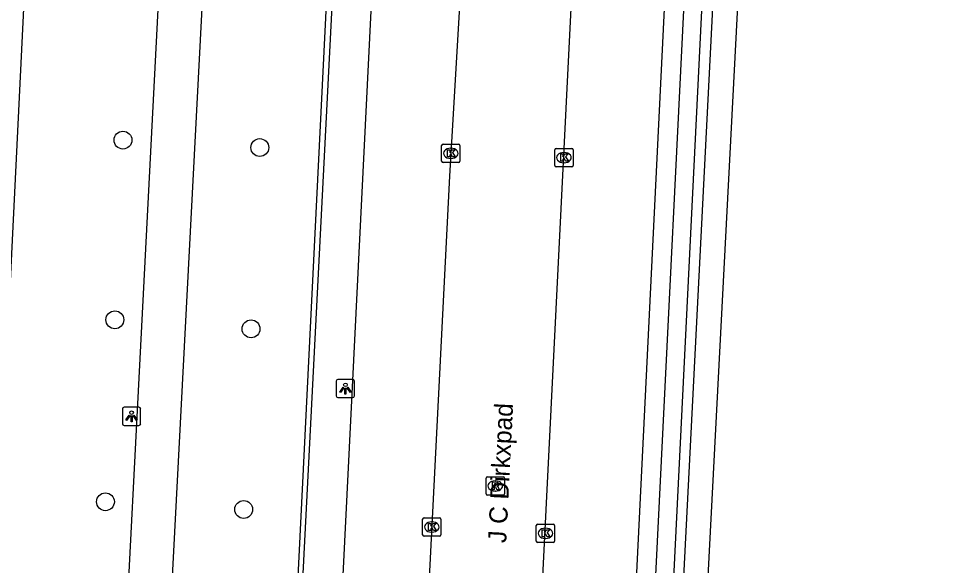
# Model space of a CAD drawing. Extents: x 161761 to 162722, y 384793 to 385405.
# Drawn here: x 162374.6 to 162426.2, y 385154.5 to 385184.4 of the extents above; entities that cross this region are included whole.
import ezdxf

# ---------------------------------------------------------------- set-up
doc = ezdxf.new("R2010")
doc.units = 0
for name, color, linetype in [('IMGEO_Boom', 7, 'Continuous'), ('IMGEO_Groenvoorziening', 7, 'Continuous'), ('IMGEO_Kolk', 7, 'Continuous'), ('IMGEO_Lichtpunt', 7, 'Continuous'), ('IMGEO_Loofbos', 7, 'Continuous'), ('IMGEO_Openbare_ruimte_label', 7, 'Continuous'), ('IMGEO_Parkeervlak_open', 7, 'Continuous'), ('IMGEO_Rijbaan_lokaal_open', 7, 'Continuous'), ('IMGEO_Rioolput', 7, 'Continuous'), ('IMGEO_Voetpad_open', 7, 'Continuous'), ('IMGEO_Waterloop', 7, 'Continuous')]:
    doc.layers.add(name, color=color, linetype=linetype)

msp = doc.modelspace()

# ---------------------------------------------------------------- linework, layer by layer
at = {"layer": 'IMGEO_Boom'}
for centre in [(162380.34, 385177.754), (162387.833, 385177.345), (162379.898, 385167.921), (162387.354, 385167.423), (162379.381, 385157.961), (162386.951, 385157.54)]:
    msp.add_circle(centre, 0.489, dxfattribs=at)
at = {"layer": 'IMGEO_Groenvoorziening'}
msp.add_lwpolyline([(162419.401, 385355.707), (162414.261, 385250), (162407.783, 385119.36)], dxfattribs=at)
at = {"layer": 'IMGEO_Kolk'}
for p, q in [((162397.792, 385176.604), (162397.792, 385177.456)), ((162397.867, 385177.53), (162398.719, 385177.53)), ((162398.28, 385177.31), (162398.305, 385177.31)), ((162398.793, 385177.456), (162398.793, 385176.604)), ((162403.989, 385176.369), (162403.989, 385177.221)), ((162404.064, 385177.295), (162404.916, 385177.295)), ((162404.99, 385177.221), (162404.99, 385176.369)), ((162398.303, 385176.75), (162398.278, 385176.75)), ((162404.477, 385177.075), (162404.502, 385177.075)), ((162398.719, 385176.53), (162397.867, 385176.53)), ((162404.916, 385176.295), (162404.064, 385176.295)), ((162404.5, 385176.515), (162404.475, 385176.515)), ((162396.826, 385157.08), (162397.678, 385157.08)), ((162396.751, 385156.154), (162396.751, 385157.006)), ((162397.239, 385156.86), (162397.264, 385156.86)), ((162397.752, 385157.006), (162397.752, 385156.154)), ((162402.974, 385155.807), (162402.974, 385156.659)), ((162403.049, 385156.733), (162403.901, 385156.733)), ((162403.975, 385156.659), (162403.975, 385155.807)), ((162397.678, 385156.08), (162396.826, 385156.08)), ((162397.262, 385156.3), (162397.237, 385156.3)), ((162403.462, 385156.513), (162403.487, 385156.513)), ((162403.901, 385155.733), (162403.049, 385155.733)), ((162403.485, 385155.953), (162403.46, 385155.953))]:
    msp.add_line(p, q, dxfattribs=at)
for points in [[(162397.792, 385176.604), (162397.792, 385177.456)], [(162397.867, 385177.53), (162398.719, 385177.53)], [(162398.113, 385177.23), (162398.236, 385177.23), (162398.236, 385177.079), (162398.366, 385177.23), (162398.53, 385177.23), (162398.384, 385177.079), (162398.537, 385176.83), (162398.385, 385176.83), (162398.3, 385176.994), (162398.236, 385176.927), (162398.236, 385176.83), (162398.113, 385176.83), (162398.113, 385177.23)], [(162398.793, 385177.456), (162398.793, 385176.604)], [(162403.989, 385176.369), (162403.989, 385177.221)], [(162404.064, 385177.295), (162404.916, 385177.295)], [(162404.99, 385177.221), (162404.99, 385176.369)], [(162404.31, 385176.995), (162404.433, 385176.995), (162404.433, 385176.844), (162404.563, 385176.995), (162404.727, 385176.995), (162404.581, 385176.844), (162404.734, 385176.595), (162404.582, 385176.595), (162404.497, 385176.759), (162404.433, 385176.692), (162404.433, 385176.595), (162404.31, 385176.595), (162404.31, 385176.995)], [(162398.719, 385176.53), (162397.867, 385176.53)], [(162404.916, 385176.295), (162404.064, 385176.295)], [(162396.826, 385157.08), (162397.678, 385157.08)], [(162396.751, 385156.154), (162396.751, 385157.006)], [(162397.072, 385156.78), (162397.195, 385156.78), (162397.195, 385156.629), (162397.325, 385156.78), (162397.489, 385156.78), (162397.343, 385156.629), (162397.496, 385156.38), (162397.344, 385156.38), (162397.259, 385156.544), (162397.195, 385156.477), (162397.195, 385156.38), (162397.072, 385156.38), (162397.072, 385156.78)], [(162397.752, 385157.006), (162397.752, 385156.154)], [(162402.974, 385155.807), (162402.974, 385156.659)], [(162403.049, 385156.733), (162403.901, 385156.733)], [(162403.975, 385156.659), (162403.975, 385155.807)], [(162397.678, 385156.08), (162396.826, 385156.08)], [(162403.295, 385156.433), (162403.418, 385156.433), (162403.418, 385156.282), (162403.548, 385156.433), (162403.712, 385156.433), (162403.566, 385156.282), (162403.719, 385156.033), (162403.567, 385156.033), (162403.482, 385156.197), (162403.418, 385156.13), (162403.418, 385156.033), (162403.295, 385156.033), (162403.295, 385156.433)], [(162403.901, 385155.733), (162403.049, 385155.733)]]:
    msp.add_lwpolyline(points, dxfattribs=at)
for centre, start, end in [((162397.869, 385177.454), 91.552, 178.448), ((162397.869, 385177.454), 91.552, 178.448), ((162398.717, 385177.454), 1.552, 88.448), ((162398.717, 385177.454), 1.552, 88.448), ((162404.066, 385177.219), 91.552, 178.448), ((162404.066, 385177.219), 91.552, 178.448), ((162404.914, 385177.219), 1.552, 88.448), ((162404.914, 385177.219), 1.552, 88.448), ((162397.869, 385176.606), 181.552, 268.448), ((162397.869, 385176.606), 181.552, 268.448), ((162398.717, 385176.606), 271.552, 358.448), ((162398.717, 385176.606), 271.552, 358.448), ((162404.066, 385176.371), 181.552, 268.448), ((162404.066, 385176.371), 181.552, 268.448), ((162404.914, 385176.371), 271.552, 358.448), ((162404.914, 385176.371), 271.552, 358.448), ((162396.828, 385157.004), 91.552, 178.448), ((162396.828, 385157.004), 91.552, 178.448), ((162397.676, 385157.004), 1.552, 88.448), ((162397.676, 385157.004), 1.552, 88.448), ((162403.051, 385156.657), 91.552, 178.448), ((162403.051, 385156.657), 91.552, 178.448), ((162403.899, 385156.657), 1.552, 88.448), ((162403.899, 385156.657), 1.552, 88.448), ((162396.828, 385156.156), 181.552, 268.448), ((162396.828, 385156.156), 181.552, 268.448), ((162397.676, 385156.156), 271.552, 358.448), ((162397.676, 385156.156), 271.552, 358.448), ((162403.051, 385155.809), 181.552, 268.448), ((162403.051, 385155.809), 181.552, 268.448), ((162403.899, 385155.809), 271.552, 358.448), ((162403.899, 385155.809), 271.552, 358.448)]:
    msp.add_arc(centre, 0.0765, start, end, dxfattribs=at)
for centre, major_axis, ratio, start_param, end_param in [((162398.279, 385177.03), (-0.387, 0.002), 0.722429, 4.712389, 7.853982), ((162398.304, 385177.03), (-0.39, 0.002), 0.717154, 1.570796, 4.712389), ((162404.476, 385176.795), (-0.387, 0.002), 0.722429, 4.712389, 7.853982), ((162404.501, 385176.795), (-0.39, 0.002), 0.717154, 1.570796, 4.712389), ((162397.238, 385156.58), (-0.387, 0.002), 0.722429, 4.712389, 7.853982), ((162397.263, 385156.58), (-0.39, 0.002), 0.717154, 1.570796, 4.712389), ((162403.461, 385156.233), (-0.387, 0.002), 0.722429, 4.712389, 7.853982), ((162403.486, 385156.233), (-0.39, 0.002), 0.717154, 1.570796, 4.712389)]:
    msp.add_ellipse(centre, major_axis=major_axis, ratio=ratio, start_param=start_param, end_param=end_param, dxfattribs=at)
at = {"layer": 'IMGEO_Lichtpunt'}
for p, q in [((162392.022, 385164.562), (162392.022, 385163.755)), ((162392.022, 385164.562), (162392.022, 385163.755)), ((162392.924, 385164.657), (162392.116, 385164.657)), ((162392.924, 385164.657), (162392.116, 385164.657)), ((162393.018, 385163.755), (162393.018, 385164.562)), ((162393.018, 385163.755), (162393.018, 385164.562)), ((162392.116, 385163.661), (162392.924, 385163.661)), ((162392.116, 385163.661), (162392.924, 385163.661)), ((162380.314, 385163.041), (162380.314, 385162.234)), ((162380.314, 385163.041), (162380.314, 385162.234)), ((162381.216, 385163.136), (162380.408, 385163.136)), ((162381.216, 385163.136), (162380.408, 385163.136)), ((162381.31, 385162.234), (162381.31, 385163.041)), ((162381.31, 385162.234), (162381.31, 385163.041)), ((162380.408, 385162.14), (162381.216, 385162.14)), ((162380.408, 385162.14), (162381.216, 385162.14))]:
    msp.add_line(p, q, dxfattribs=at)
for points in [[(162392.396, 385164.226), (162392.435, 385164.198), (162392.247, 385163.936), (162392.209, 385163.963), (162392.396, 385164.226)], [(162392.498, 385164.178), (162392.545, 385164.178), (162392.545, 385163.856), (162392.498, 385163.856), (162392.498, 385164.178)], [(162392.608, 385164.198), (162392.646, 385164.225), (162392.833, 385163.963), (162392.794, 385163.935), (162392.608, 385164.198)], [(162380.688, 385162.705), (162380.727, 385162.677), (162380.539, 385162.415), (162380.501, 385162.442), (162380.688, 385162.705)], [(162380.79, 385162.657), (162380.837, 385162.657), (162380.837, 385162.335), (162380.79, 385162.335), (162380.79, 385162.657)], [(162380.9, 385162.677), (162380.938, 385162.704), (162381.125, 385162.442), (162381.086, 385162.414), (162380.9, 385162.677)]]:
    msp.add_lwpolyline(points, dxfattribs=at)
for centre in [(162392.521, 385164.36), (162380.813, 385162.839)]:
    msp.add_circle(centre, 0.0994, dxfattribs=at)
for centre, start, end in [((162392.116, 385164.562), 90, 180), ((162392.116, 385164.562), 90, 180), ((162392.924, 385164.562), 0, 90), ((162392.924, 385164.562), 0, 90), ((162392.116, 385163.755), 180, 270), ((162392.116, 385163.755), 180, 270), ((162392.924, 385163.755), 270, 0), ((162392.924, 385163.755), 270, 360), ((162380.408, 385163.041), 90, 180), ((162380.408, 385163.041), 90, 180), ((162381.216, 385163.041), 0, 90), ((162381.216, 385163.041), 0, 90), ((162380.408, 385162.234), 180, 270), ((162380.408, 385162.234), 180, 270), ((162381.216, 385162.234), 270, 0), ((162381.216, 385162.234), 270, 360)]:
    msp.add_arc(centre, 0.0946, start, end, dxfattribs=at)
at = {"layer": 'IMGEO_Loofbos'}
msp.add_lwpolyline([(162408.166, 385119.329), (162410.582, 385119.132), (162417.396, 385250), (162419.486, 385290.14), (162434.994, 385289.014), (162477.196, 385287.088)], dxfattribs=at)
at = {"layer": 'IMGEO_Parkeervlak_open'}
msp.add_lwpolyline([(162407.031, 385124.711), (162413.183, 385250), (162418.351, 385355.761)], dxfattribs=at)
at = {"layer": 'IMGEO_Rijbaan_lokaal_open'}
for points in [[(162401.858, 385124.206), (162405.723, 385201.838), (162408.073, 385250), (162413.519, 385357.905)], [(162399.96, 385205.26), (162398.225, 385175.788), (162396.601, 385143.694), (162395.525, 385124.911)]]:
    msp.add_lwpolyline(points, dxfattribs=at)
at = {"layer": 'IMGEO_Rioolput'}
for p, q in [((162400.228, 385158.4), (162400.228, 385159.252)), ((162400.303, 385159.326), (162401.155, 385159.326)), ((162401.229, 385159.252), (162401.229, 385158.4)), ((162400.716, 385159.106), (162400.741, 385159.106)), ((162401.155, 385158.326), (162400.303, 385158.326)), ((162400.739, 385158.546), (162400.714, 385158.546))]:
    msp.add_line(p, q, dxfattribs=at)
for points in [[(162400.228, 385158.4), (162400.228, 385159.252)], [(162400.303, 385159.326), (162401.155, 385159.326)], [(162401.229, 385159.252), (162401.229, 385158.4)], [(162400.817, 385159.024), (162400.565, 385159.026), (162400.565, 385158.626)], [(162400.565, 385158.626), (162400.689, 385158.626), (162400.689, 385158.788), (162400.7, 385158.788)], [(162400.743, 385158.945), (162400.689, 385158.945), (162400.689, 385158.864)], [(162400.689, 385158.864), (162400.741, 385158.864)], [(162400.747, 385158.759), (162400.818, 385158.626), (162400.958, 385158.626), (162400.893, 385158.752)], [(162401.155, 385158.326), (162400.303, 385158.326)]]:
    msp.add_lwpolyline(points, dxfattribs=at)
for centre, radius, start, end in [((162400.305, 385159.25), 0.0765, 91.552, 178.448), ((162400.305, 385159.25), 0.0765, 91.552, 178.448), ((162401.153, 385159.25), 0.0765, 1.552, 88.448), ((162401.153, 385159.25), 0.0765, 1.552, 88.448), ((162400.699, 385158.735), 0.0533, 26.0293, 88.6989), ((162400.725, 385159.053), 0.19, 274.7715, 282.9687), ((162400.749, 385158.849), 0.0964, 77.0061, 93.1865), ((162400.763, 385158.906), 0.0378, 276.6634, 79.6772), ((162400.816, 385158.914), 0.109, 350.3612, 89.416), ((162400.814, 385158.914), 0.112, 277.5842, 350.9817), ((162400.798, 385158.699), 0.108, 29.5134, 73.7905), ((162400.305, 385158.402), 0.0765, 181.552, 268.448), ((162400.305, 385158.402), 0.0765, 181.552, 268.448), ((162401.153, 385158.402), 0.0765, 271.552, 358.448), ((162401.153, 385158.402), 0.0765, 271.552, 358.448)]:
    msp.add_arc(centre, radius, start, end, dxfattribs=at)
for centre, major_axis, ratio, start_param, end_param in [((162400.715, 385158.826), (-0.387, 0.002), 0.722429, 4.712389, 7.853982), ((162400.74, 385158.826), (-0.39, 0.002), 0.717154, 1.570796, 4.712389)]:
    msp.add_ellipse(centre, major_axis=major_axis, ratio=ratio, start_param=start_param, end_param=end_param, dxfattribs=at)
at = {"layer": 'IMGEO_Voetpad_open'}
for points in [[(162383.659, 385212.173), (162383.322, 385205.522), (162382.945, 385198.235), (162382.934, 385198.021), (162378.774, 385117.666), (162378.573, 385113.77)], [(162380.956, 385113.644), (162385.508, 385200.73), (162386.032, 385210.754), (162390.105, 385210.57), (162390.046, 385209.276), (162392.658, 385209.158)], [(162393.065, 385210.435), (162392.956, 385208.286), (162388.217, 385115.486)], [(162392.658, 385209.158), (162388.017, 385115.498)], [(162252.438, 385124.368), (162260.02, 385123.94), (162263.947, 385204.122), (162305.338, 385201.976), (162306.297, 385202.545), (162323.152, 385201.672), (162323.31, 385204.714), (162333.392, 385204.192), (162333.234, 385201.15), (162334.178, 385200.507), (162375.558, 385198.374), (162371.403, 385114.132)], [(162397.822, 385203.463), (162394.837, 385203.586), (162390.982, 385125.656)]]:
    msp.add_lwpolyline(points, dxfattribs=at)
at = {"layer": 'IMGEO_Waterloop'}
msp.add_lwpolyline([(162418.132, 385293.078), (162476.312, 385290.198), (162475.895, 385288.42), (162418.045, 385291.37), (162409.407, 385121.965), (162408.945, 385121.989), (162420.33, 385352.734), (162421.172, 385352.691), (162418.132, 385293.078)], dxfattribs=at)

# ---------------------------------------------------------------- texts
at = {"layer": 'IMGEO_Openbare_ruimte_label'}
msp.add_text('J C Dirkxpad', height=1, rotation=87.1347, dxfattribs=at).set_placement((162401.326, 385155.689))

doc.saveas('drawing.dxf')
